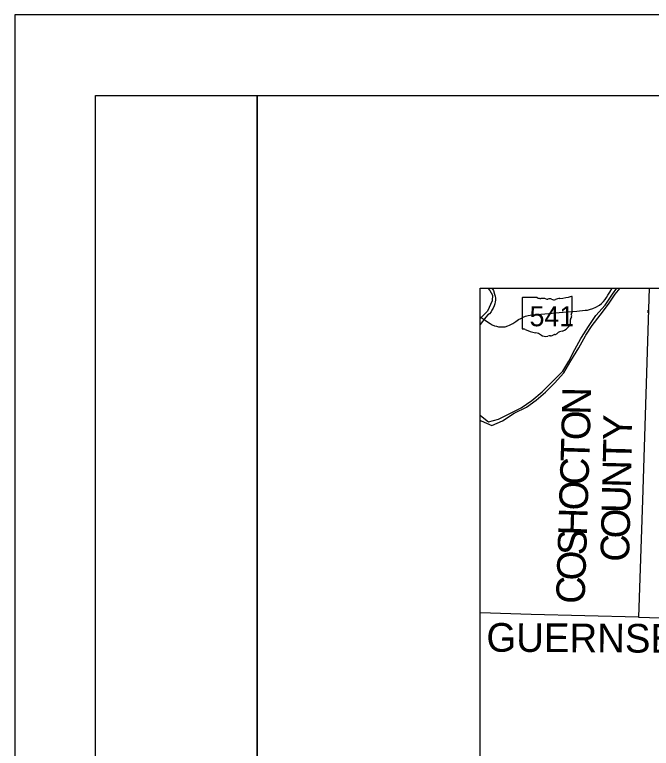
# Model space of a CAD drawing. Extents: x -12.1 to 34, y 0 to 22.
# Drawn here: x 0 to 3.941, y 17.456 to 22 of the extents above; entities that cross this region are included whole.
import ezdxf

# ---------------------------------------------------------------- set-up
doc = ezdxf.new("R2010")
doc.units = 0
for name, color, linetype in [('GM_X_County', 7, 'Continuous'), ('GM_X_County_Text', 7, 'Continuous'), ('GM_X_Major_River', 7, 'Continuous'), ('GM_X_Minor_Lake', 7, 'Continuous'), ('GM_X_Minor_River', 7, 'Continuous'), ('GM_X_State_Route', 7, 'Continuous'), ('GM_X_State_Shield', 7, 'Continuous'), ('GM_X_Township', 7, 'Continuous'), ('SH_Border', 7, 'Continuous'), ('SH_Cut_Line', 7, 'Continuous'), ('SH_Text', 7, 'Continuous')]:
    doc.layers.add(name, color=color, linetype=linetype)

msp = doc.modelspace()

# ---------------------------------------------------------------- linework, layer by layer
at = {"layer": 'GM_X_County'}
msp.add_lwpolyline([(3.928, 20.3063), (3.8856, 18.9924), (3.8609, 18.2681), (3.1963, 18.2855), (2.8817, 18.2946)], dxfattribs=at)
at = {"layer": 'GM_X_Major_River'}
for points in [[(2.9298, 20.3063), (2.9413, 20.2913), (2.9567, 20.2628), (2.955, 20.227), (2.9266, 20.1644), (2.8817, 20.1176)], [(2.8817, 19.4889), (2.8866, 19.484), (2.9537, 19.4555), (3.0187, 19.4842), (3.0913, 19.5312), (3.1691, 19.568), (3.2289, 19.6116), (3.2852, 19.6616), (3.3422, 19.7169), (3.3997, 19.7814), (3.443, 19.8549), (3.4914, 19.9355), (3.5326, 20.0104), (3.5362, 20.0143), (3.5745, 20.074), (3.6241, 20.1392), (3.6749, 20.2059), (3.7167, 20.2687), (3.7473, 20.3063)], [(2.8817, 19.5191), (2.8837, 19.5178), (2.9323, 19.478), (2.9943, 19.4946), (3.0651, 19.5293), (3.1361, 19.5654), (3.2019, 19.6103), (3.265, 19.6645), (3.393, 19.7925), (3.4306, 19.8547), (3.4679, 19.9261), (3.5045, 19.995), (3.5077, 20.0007), (3.5528, 20.0677), (3.5983, 20.1373), (3.6546, 20.2014), (3.7015, 20.2681), (3.7281, 20.3063)], [(2.9524, 20.3063), (2.9527, 20.3057), (2.9629, 20.2915), (2.9709, 20.2698), (2.9751, 20.2573), (2.9768, 20.2438), (2.9763, 20.2325), (2.9745, 20.2205), (2.9719, 20.2088), (2.9679, 20.1964), (2.9615, 20.1826), (2.9543, 20.1699), (2.9493, 20.1603), (2.9396, 20.148), (2.9293, 20.1406)], [(2.9293, 20.1406), (2.9161, 20.1269), (2.8817, 20.0801)]]:
    msp.add_lwpolyline(points, dxfattribs=at)
at = {"layer": 'GM_X_Minor_Lake'}
msp.add_line((3.921, 20.1541), (3.9215, 20.1695), dxfattribs=at)
at = {"layer": 'GM_X_Minor_River'}
msp.add_lwpolyline([(3.8629, 18.3051), (3.863, 18.3044)], dxfattribs=at)
at = {"layer": 'GM_X_State_Route'}
msp.add_lwpolyline([(2.8817, 20.128), (2.9118, 20.1074), (2.9261, 20.0975), (2.9425, 20.0861), (2.956, 20.0787), (2.9699, 20.0731), (2.9815, 20.0696), (2.9947, 20.0669), (3.0093, 20.0657), (3.0221, 20.0657), (3.0353, 20.0673), (3.0524, 20.0717), (3.0639, 20.0761), (3.0755, 20.082), (3.0826, 20.0867), (3.1015, 20.1), (3.118, 20.1111), (3.1322, 20.1187), (3.1473, 20.1261), (3.1628, 20.1321), (3.1792, 20.1366), (3.1915, 20.1388), (3.2034, 20.1406), (3.2563, 20.1451), (3.3072, 20.1492), (3.3704, 20.1553), (3.42, 20.1596), (3.4801, 20.1641), (3.5321, 20.1687), (3.5464, 20.1706), (3.5574, 20.1733), (3.5785, 20.1796), (3.5982, 20.1884), (3.6192, 20.2), (3.6317, 20.2101), (3.6438, 20.2225), (3.6551, 20.2359), (3.6642, 20.2489), (3.6723, 20.262), (3.6842, 20.2821), (3.6982, 20.3055), (3.6987, 20.3063)], dxfattribs=at)
at = {"layer": 'GM_X_State_Shield'}
for p, q in [((3.1416, 20.2444), (3.1416, 20.0568)), ((3.2352, 20.2476), (3.1447, 20.2476)), ((3.4506, 20.1541), (3.4506, 20.2523)), ((3.4506, 20.1542), (3.4506, 20.1541))]:
    msp.add_line(p, q, dxfattribs=at)
for centre, major_axis, start_param, end_param in [((3.1452, 20.2448), (0.00358, 0), 1.712693, 3.28349), ((3.2567, 20.2694), (0.0347, 0), 4.042523, 4.731795), ((3.2682, 20.1423), (0.1246, 0), 1.404758, 1.657858), ((3.2965, 20.2458), (0.01, 0), 3.836095, 5.185415), ((3.3112, 20.2241), (0.0208, 0), 0.950623, 2.079405), ((3.3381, 20.2538), (0.0251, 0), 4.081561, 5.145723), ((3.3824, 20.1903), (0.0659, 0), 1.699011, 2.107814), ((3.3406, 20.5034), (0.3277, 0), 4.814394, 5.042369), ((3.4472, 20.2527), (0.00344, 0), 6.141152, 7.989035), ((3.4498, 20.1469), (0.00532, 0), 1.883978, 3.671073), ((3.416, 20.1345), (0.032, 0), 5.934695, 6.695948), ((3.447, 20.1538), (0.00368, 0), 5.05454, 6.418171), ((3.3589, 20.1006), (0.082, 0), 5.101752, 6.440018), ((3.463, 20.1131), (0.0232, 0), 2.387724, 3.262537), ((3.1452, 20.0564), (0.00361, 0), 3.00124, 4.508301), ((3.1458, 20.0756), (0.0276, 0), 4.665946, 4.897461), ((3.1514, 20.046), (0.00994, 0), 0.519207, 1.627899), ((3.2769, 20.2145), (0.2366, 0), 4.195997, 4.488961), ((3.2063, 19.9725), (0.074, 0), 0.823519, 1.323587), ((3.2864, 20.045), (0.047, 0), 4.026481, 4.996735), ((3.3135, 19.9802), (0.0386, 0), 1.495662, 1.94098), ((3.317, 20.031), (0.025, 0), 4.691044, 5.507374), ((3.3396, 20.0128), (0.00705, 0), 1.147584, 2.315152), ((3.3366, 20.0386), (0.0265, 0), 4.937069, 5.64225), ((3.3935, 20.0041), (0.0449, 0), 1.647645, 2.488434)]:
    msp.add_ellipse(centre, major_axis=major_axis, ratio=0.8, start_param=start_param, end_param=end_param, dxfattribs=at)
at = {"layer": 'GM_X_Township'}
msp.add_lwpolyline([(3.8609, 18.2681), (4.5421, 18.2476)], dxfattribs=at)
at = {"layer": 'SH_Border'}
for points in [[(0.5, 21.5), (1.5, 21.5), (1.5, 0.5), (0.5, 0.5)], [(1.5, 21.5), (33.5, 21.5), (33.5, 0.5), (1.5, 0.5)]]:
    msp.add_lwpolyline(points, close=True, dxfattribs=at)
at = {"layer": 'SH_Cut_Line'}
msp.add_lwpolyline([(0, 0), (34, 0), (34, 22), (0, 22)], close=True, dxfattribs=at)
at = {"layer": 'SH_Text'}
msp.add_lwpolyline([(2.8817, 20.3063), (10.5897, 20.3063), (10.5897, 10.9773), (2.8817, 10.9773)], close=True, dxfattribs=at)

# ---------------------------------------------------------------- texts
at = {"layer": 'GM_X_County_Text'}
for s, height, rotation, p in [('N', 0.1776, 88.9622, (3.5645, 19.5202)), ('O', 0.1776, 88.469, (3.5603, 19.3619)), ('Y', 0.1776, 88.6358, (3.8184, 19.3618)), ('T', 0.1776, 88.2126, (3.5562, 19.2285)), ('T', 0.1776, 88.6358, (3.8176, 19.2243)), ('C', 0.1776, 88.1616, (3.5515, 19.0837)), ('N', 0.1776, 88.6373, (3.8139, 19.0676)), ('O', 0.1776, 88.1583, (3.5465, 18.927)), ('U', 0.1776, 88.6368, (3.8102, 18.911)), ('H', 0.1776, 88.1594, (3.5414, 18.7704)), ('O', 0.1776, 88.6499, (3.8065, 18.7543)), ('S', 0.1776, 88.159, (3.5376, 18.6497)), ('C', 0.1776, 88.7376, (3.8033, 18.6097)), ('O', 0.1776, 88.1594, (3.5325, 18.4931)), ('C', 0.1776, 88.1594, (3.5279, 18.3484)), ('GUERNSEY', 0.17756, 359.6417, (2.9193, 18.0545))]:
    msp.add_text(s, height=height, rotation=rotation, dxfattribs=at).set_placement(p)
at = {"layer": 'GM_X_State_Shield'}
msp.add_text('541', height=0.1236, dxfattribs=at).set_placement((3.1872, 20.07))

doc.saveas('drawing.dxf')
